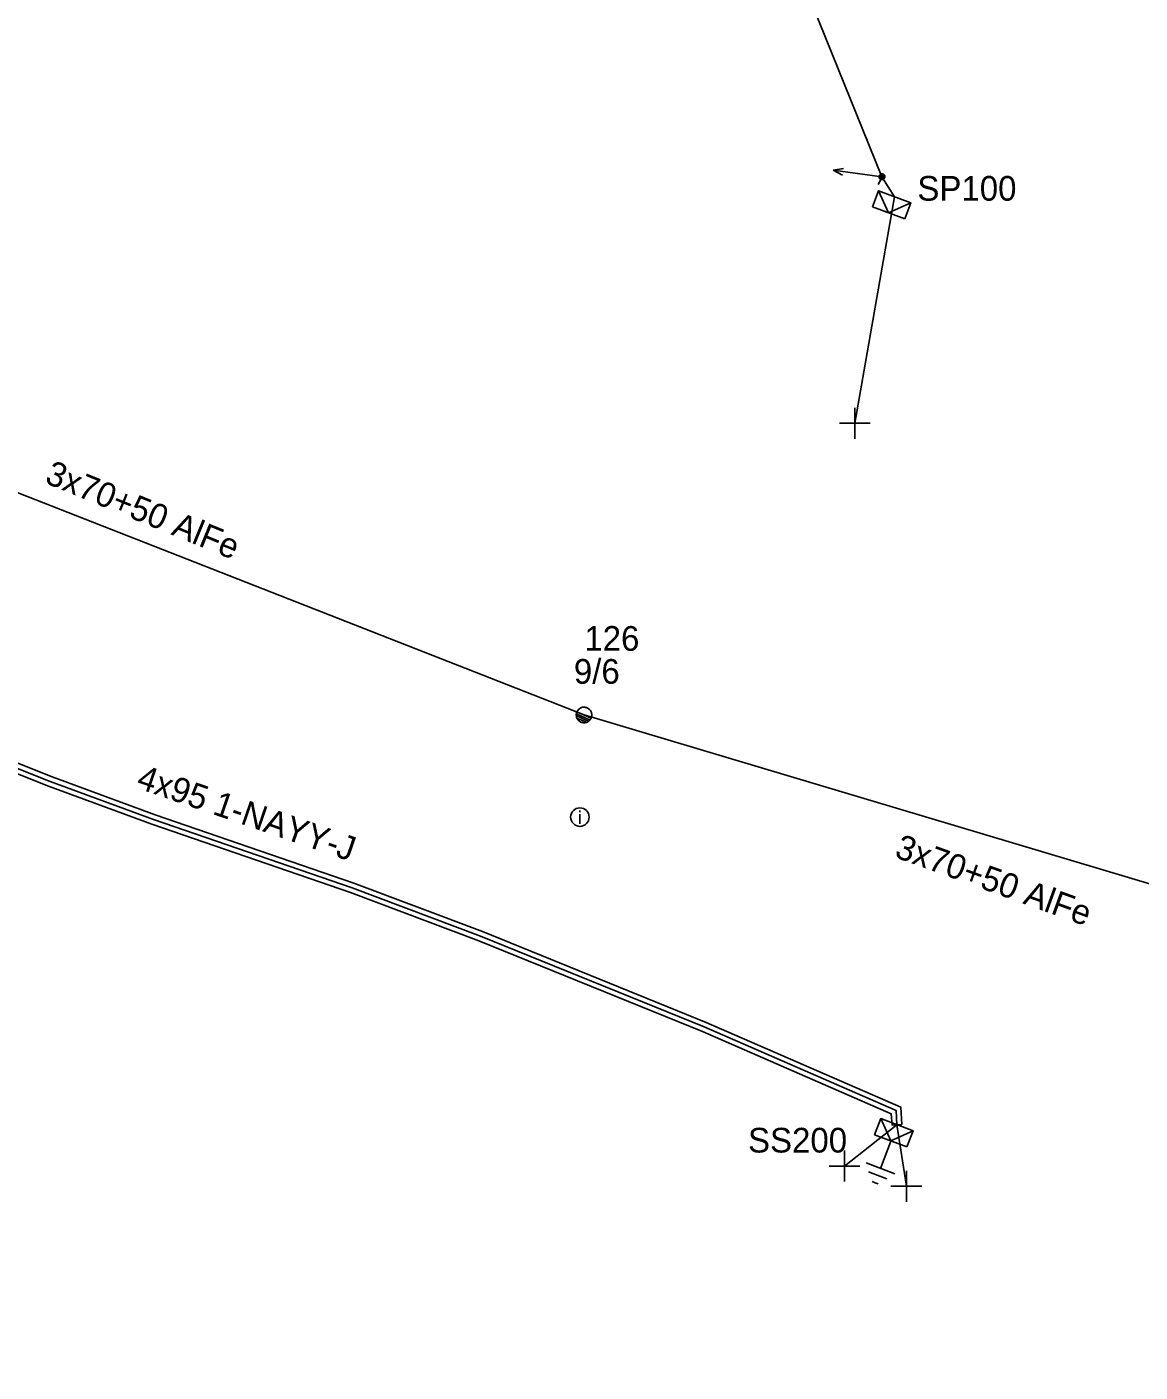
# Model space of a CAD drawing. Extents: x -748492 to -735633, y -1146251 to -1139940.
# Drawn here: x -740483.4 to -740438.3, y -1142129.4 to -1142074.9 of the extents above; entities that cross this region are included whole.
import ezdxf

# ---------------------------------------------------------------- set-up
doc = ezdxf.new("R2010")
doc.units = 0
for name, color, linetype in [('Vrstva 1', 7, 'Continuous'), ('Vrstva 10', 7, 'Continuous'), ('Vrstva 12', 7, 'Continuous'), ('Vrstva 13', 7, 'Continuous'), ('Vrstva 14', 7, 'Continuous'), ('Vrstva 15', 7, 'Continuous'), ('Vrstva 2', 7, 'Continuous'), ('Vrstva 20', 7, 'Continuous'), ('Vrstva 31', 7, 'Continuous'), ('Vrstva 33', 7, 'Continuous'), ('Vrstva 34', 7, 'Continuous'), ('Vrstva 36', 7, 'Continuous'), ('Vrstva 5', 7, 'Continuous'), ('Vrstva 59', 7, 'Continuous'), ('Vrstva 6', 7, 'Continuous'), ('Vrstva 8', 7, 'Continuous'), ('Vrstva 9', 7, 'Continuous')]:
    doc.layers.add(name, color=color, linetype=linetype)

# ---------------------------------------------------------------- blocks, each defined once
blk = doc.blocks.new('NN440')
at = {"layer": 'Vrstva 2'}
for points in [[(0.63, 0), (0.63, 0.06), (0.62, 0.13), (0.6, 0.19), (0.58, 0.25), (0.55, 0.31), (0.51, 0.37), (0.47, 0.42), (0.42, 0.46), (0.37, 0.51), (0.32, 0.54), (0.26, 0.57), (0.2, 0.59), (0.13, 0.61), (0.07, 0.62), (0, 0.63), (-0.06, 0.62), (-0.13, 0.61), (-0.19, 0.59), (-0.26, 0.57), (-0.31, 0.54), (-0.37, 0.51), (-0.42, 0.46), (-0.47, 0.42), (-0.51, 0.37), (-0.54, 0.31), (-0.57, 0.25), (-0.6, 0.19), (-0.62, 0.13), (-0.63, 0.06), (-0.63, 0), (-0.63, -0.07), (-0.62, -0.14), (-0.6, -0.2), (-0.57, -0.26), (-0.54, -0.32), (-0.51, -0.37), (-0.47, -0.43), (-0.42, -0.47), (-0.37, -0.51), (-0.31, -0.55), (-0.26, -0.58), (-0.19, -0.6), (-0.13, -0.62), (-0.06, -0.63), (0, -0.63), (0.07, -0.63), (0.13, -0.62), (0.2, -0.6), (0.26, -0.58), (0.32, -0.55), (0.37, -0.51), (0.42, -0.47), (0.47, -0.43), (0.51, -0.37), (0.55, -0.32), (0.58, -0.26), (0.6, -0.2), (0.62, -0.14), (0.63, -0.07), (0.63, 0)], [(-0.63, 0), (0.63, 0)], [(-0.6, -0.18), (0.57, -0.18)], [(-0.51, -0.32), (0.5, -0.32)], [(-0.37, -0.47), (0.35, -0.47)]]:
    blk.add_lwpolyline(points, dxfattribs=at)
blk = doc.blocks.new('NN560')
at = {"layer": 'Vrstva 2'}
for points in [[(1.999, -0.001), (1.59, 0.141)], [(0, -0.001), (1.999, -0.001)], [(1.999, -0.001), (1.59, -0.134)]]:
    blk.add_lwpolyline(points, dxfattribs=at)
blk = doc.blocks.new('NN770')
at = {"layer": 'Vrstva 10'}
for p, q in [((0.002, 0.187), (0.002, 0.263)), ((0.002, -0.276), (0.002, 0.111))]:
    blk.add_line(p, q, dxfattribs=at)
blk.add_circle((0, -0.008), 0.375, dxfattribs=at)
blk = doc.blocks.new('NN800')
at = {"layer": 'Vrstva 1'}
for points in [[(-0.442, 0.442), (0.442, -0.442)], [(-0.442, -0.442), (0.442, 0.442)]]:
    blk.add_lwpolyline(points, dxfattribs=at)
blk = doc.blocks.new('NN630')
at = {"layer": 'Vrstva 9'}
for points in [[(-0.003, -0.7), (-0.703, 0)], [(-0.703, -0.7), (-0.703, 0), (0.697, 0), (0.697, -0.7)], [(-0.003, -0.7), (0.697, 0)], [(-0.703, -0.7), (0.697, -0.7)]]:
    blk.add_lwpolyline(points, dxfattribs=at)
blk = doc.blocks.new('NN810')
at = {"layer": 'Vrstva 14'}
for points in [[(0.004, -0.64), (0.004, -1.89)], [(0.629, -1.89), (-0.621, -1.89)], [(0.388, -2.2), (-0.399, -2.2)], [(0.004, -2.515), (-0.124, -2.515)], [(0.137, -2.515), (0.004, -2.515)]]:
    blk.add_lwpolyline(points, dxfattribs=at)
blk = doc.blocks.new('NN500')
at = {"layer": 'Vrstva 2'}
for points in [[(0, -0.24), (0.02, -0.23), (0.05, -0.23), (0.07, -0.22), (0.09, -0.22), (0.12, -0.2), (0.14, -0.19), (0.16, -0.18), (0.17, -0.16), (0.19, -0.14), (0.2, -0.12), (0.21, -0.1), (0.22, -0.07), (0.23, -0.05), (0.23, -0.02), (0.23, 0), (0.23, 0.02), (0.23, 0.05), (0.22, 0.07), (0.21, 0.1), (0.2, 0.12), (0.19, 0.14), (0.17, 0.16), (0.16, 0.17), (0.14, 0.19), (0.12, 0.2), (0.09, 0.21), (0.07, 0.22), (0.05, 0.23), (0.02, 0.23), (0, 0.23), (-0.03, 0.23), (-0.05, 0.23), (-0.07, 0.22), (-0.1, 0.21), (-0.12, 0.2), (-0.14, 0.19), (-0.16, 0.17), (-0.18, 0.16), (-0.19, 0.14), (-0.2, 0.12), (-0.22, 0.1), (-0.22, 0.07), (-0.23, 0.05), (-0.23, 0.02), (-0.24, 0), (-0.23, -0.02), (-0.23, -0.05), (-0.22, -0.07), (-0.22, -0.1), (-0.2, -0.12), (-0.19, -0.14), (-0.18, -0.16), (-0.16, -0.18), (-0.14, -0.19), (-0.12, -0.2), (-0.1, -0.22), (-0.07, -0.22), (-0.05, -0.23), (-0.03, -0.23), (0, -0.24)], [(0, -0.24), (0.02, -0.23), (0.05, -0.23), (0.07, -0.22), (0.09, -0.22), (0.12, -0.2), (0.14, -0.19), (0.16, -0.18), (0.17, -0.16), (0.19, -0.14), (0.2, -0.12), (0.21, -0.1), (0.22, -0.07), (0.23, -0.05), (0.23, -0.02), (0.23, 0), (0.23, 0.02), (0.23, 0.05), (0.22, 0.07), (0.21, 0.1), (0.2, 0.12), (0.19, 0.14), (0.17, 0.16), (0.16, 0.17), (0.14, 0.19), (0.12, 0.2), (0.09, 0.21), (0.07, 0.22), (0.05, 0.23), (0.02, 0.23), (0, 0.23), (-0.03, 0.23), (-0.05, 0.23), (-0.07, 0.22), (-0.1, 0.21), (-0.12, 0.2), (-0.14, 0.19), (-0.16, 0.17), (-0.18, 0.16), (-0.19, 0.14), (-0.2, 0.12), (-0.22, 0.1), (-0.22, 0.07), (-0.23, 0.05), (-0.23, 0.02), (-0.24, 0), (-0.23, -0.02), (-0.23, -0.05), (-0.22, -0.07), (-0.22, -0.1), (-0.2, -0.12), (-0.19, -0.14), (-0.18, -0.16), (-0.16, -0.18), (-0.14, -0.19), (-0.12, -0.2), (-0.1, -0.22), (-0.07, -0.22), (-0.05, -0.23), (-0.03, -0.23), (0, -0.24)], [(0, -0.21), (0.02, -0.2), (0.04, -0.2), (0.06, -0.2), (0.08, -0.19), (0.1, -0.18), (0.12, -0.17), (0.14, -0.15), (0.15, -0.14), (0.16, -0.12), (0.18, -0.1), (0.19, -0.08), (0.19, -0.06), (0.2, -0.04), (0.2, -0.02), (0.2, 0), (0.2, 0.02), (0.2, 0.04), (0.19, 0.06), (0.19, 0.08), (0.18, 0.1), (0.16, 0.12), (0.15, 0.14), (0.14, 0.15), (0.12, 0.17), (0.1, 0.18), (0.08, 0.19), (0.06, 0.19), (0.04, 0.2), (0.02, 0.2), (0, 0.2), (-0.02, 0.2), (-0.04, 0.2), (-0.06, 0.19), (-0.08, 0.19), (-0.1, 0.18), (-0.12, 0.17), (-0.14, 0.15), (-0.15, 0.14), (-0.17, 0.12), (-0.18, 0.1), (-0.19, 0.08), (-0.2, 0.06), (-0.2, 0.04), (-0.21, 0.02), (-0.21, 0), (-0.21, -0.02), (-0.2, -0.04), (-0.2, -0.06), (-0.19, -0.08), (-0.18, -0.1), (-0.17, -0.12), (-0.15, -0.14), (-0.14, -0.15), (-0.12, -0.17), (-0.1, -0.18), (-0.08, -0.19), (-0.06, -0.2), (-0.04, -0.2), (-0.02, -0.2), (0, -0.21)], [(0, -0.18), (0.02, -0.18), (0.04, -0.17), (0.05, -0.17), (0.07, -0.16), (0.09, -0.15), (0.1, -0.14), (0.12, -0.13), (0.13, -0.12), (0.14, -0.1), (0.15, -0.09), (0.16, -0.07), (0.17, -0.05), (0.17, -0.04), (0.17, -0.02), (0.17, 0), (0.17, 0.02), (0.17, 0.04), (0.17, 0.05), (0.16, 0.07), (0.15, 0.09), (0.14, 0.1), (0.13, 0.12), (0.12, 0.13), (0.1, 0.14), (0.09, 0.15), (0.07, 0.16), (0.05, 0.17), (0.04, 0.17), (0.02, 0.17), (0, 0.18), (-0.02, 0.17), (-0.04, 0.17), (-0.06, 0.17), (-0.07, 0.16), (-0.09, 0.15), (-0.1, 0.14), (-0.12, 0.13), (-0.13, 0.12), (-0.14, 0.1), (-0.15, 0.09), (-0.16, 0.07), (-0.17, 0.05), (-0.17, 0.04), (-0.18, 0.02), (-0.18, 0), (-0.18, -0.02), (-0.17, -0.04), (-0.17, -0.05), (-0.16, -0.07), (-0.15, -0.09), (-0.14, -0.1), (-0.13, -0.12), (-0.12, -0.13), (-0.1, -0.14), (-0.09, -0.15), (-0.07, -0.16), (-0.06, -0.17), (-0.04, -0.17), (-0.02, -0.18), (0, -0.18)], [(0, -0.15), (0.01, -0.15), (0.03, -0.14), (0.04, -0.14), (0.06, -0.13), (0.07, -0.13), (0.08, -0.12), (0.1, -0.11), (0.11, -0.1), (0.12, -0.09), (0.13, -0.07), (0.13, -0.06), (0.14, -0.05), (0.14, -0.03), (0.14, -0.02), (0.14, 0), (0.14, 0.01), (0.14, 0.03), (0.14, 0.04), (0.13, 0.06), (0.13, 0.07), (0.12, 0.09), (0.11, 0.1), (0.1, 0.11), (0.08, 0.12), (0.07, 0.13), (0.06, 0.13), (0.04, 0.14), (0.03, 0.14), (0.01, 0.14), (0, 0.15), (-0.02, 0.14), (-0.03, 0.14), (-0.05, 0.14), (-0.06, 0.13), (-0.07, 0.13), (-0.09, 0.12), (-0.1, 0.11), (-0.11, 0.1), (-0.12, 0.09), (-0.13, 0.07), (-0.13, 0.06), (-0.14, 0.04), (-0.14, 0.03), (-0.15, 0.01), (-0.15, 0), (-0.15, -0.02), (-0.14, -0.03), (-0.14, -0.05), (-0.13, -0.06), (-0.13, -0.07), (-0.12, -0.09), (-0.11, -0.1), (-0.1, -0.11), (-0.09, -0.12), (-0.07, -0.13), (-0.06, -0.13), (-0.05, -0.14), (-0.03, -0.14), (-0.02, -0.15), (0, -0.15)], [(0, -0.12), (0.01, -0.12), (0.02, -0.11), (0.03, -0.11), (0.05, -0.11), (0.06, -0.1), (0.07, -0.09), (0.08, -0.09), (0.09, -0.08), (0.09, -0.07), (0.1, -0.06), (0.11, -0.05), (0.11, -0.04), (0.11, -0.02), (0.11, -0.01), (0.12, 0), (0.11, 0.01), (0.11, 0.02), (0.11, 0.04), (0.11, 0.05), (0.1, 0.06), (0.09, 0.07), (0.09, 0.08), (0.08, 0.09), (0.07, 0.09), (0.06, 0.1), (0.05, 0.11), (0.03, 0.11), (0.02, 0.11), (0.01, 0.12), (0, 0.12), (-0.01, 0.12), (-0.03, 0.11), (-0.04, 0.11), (-0.05, 0.11), (-0.06, 0.1), (-0.07, 0.09), (-0.08, 0.09), (-0.09, 0.08), (-0.1, 0.07), (-0.1, 0.06), (-0.11, 0.05), (-0.11, 0.04), (-0.12, 0.02), (-0.12, 0.01), (-0.12, 0), (-0.12, -0.01), (-0.12, -0.02), (-0.11, -0.04), (-0.11, -0.05), (-0.1, -0.06), (-0.1, -0.07), (-0.09, -0.08), (-0.08, -0.09), (-0.07, -0.09), (-0.06, -0.1), (-0.05, -0.11), (-0.04, -0.11), (-0.03, -0.11), (-0.01, -0.12), (0, -0.12)], [(0, -0.09), (0.01, -0.09), (0.02, -0.09), (0.03, -0.08), (0.03, -0.08), (0.04, -0.08), (0.05, -0.07), (0.06, -0.07), (0.06, -0.06), (0.07, -0.05), (0.07, -0.04), (0.08, -0.04), (0.08, -0.03), (0.08, -0.02), (0.09, -0.01), (0.09, 0), (0.09, 0.01), (0.08, 0.02), (0.08, 0.03), (0.08, 0.03), (0.07, 0.04), (0.07, 0.05), (0.06, 0.06), (0.06, 0.06), (0.05, 0.07), (0.04, 0.07), (0.03, 0.08), (0.03, 0.08), (0.02, 0.08), (0.01, 0.09), (0, 0.09), (-0.01, 0.09), (-0.02, 0.08), (-0.03, 0.08), (-0.04, 0.08), (-0.04, 0.07), (-0.05, 0.07), (-0.06, 0.06), (-0.07, 0.06), (-0.07, 0.05), (-0.08, 0.04), (-0.08, 0.03), (-0.08, 0.03), (-0.09, 0.02), (-0.09, 0.01), (-0.09, 0), (-0.09, -0.01), (-0.09, -0.02), (-0.08, -0.03), (-0.08, -0.04), (-0.08, -0.04), (-0.07, -0.05), (-0.07, -0.06), (-0.06, -0.07), (-0.05, -0.07), (-0.04, -0.08), (-0.04, -0.08), (-0.03, -0.08), (-0.02, -0.09), (-0.01, -0.09), (0, -0.09)], [(0, -0.06), (0, -0.06), (0.01, -0.06), (0.02, -0.05), (0.02, -0.05), (0.03, -0.05), (0.03, -0.05), (0.04, -0.04), (0.04, -0.04), (0.05, -0.03), (0.05, -0.03), (0.05, -0.02), (0.05, -0.02), (0.05, -0.01), (0.06, -0.01), (0.06, 0), (0.06, 0.01), (0.05, 0.01), (0.05, 0.02), (0.05, 0.02), (0.05, 0.03), (0.05, 0.03), (0.04, 0.04), (0.04, 0.04), (0.03, 0.05), (0.03, 0.05), (0.02, 0.05), (0.02, 0.05), (0.01, 0.06), (0, 0.06), (0, 0.06), (-0.01, 0.06), (-0.01, 0.06), (-0.02, 0.05), (-0.02, 0.05), (-0.03, 0.05), (-0.03, 0.05), (-0.04, 0.04), (-0.04, 0.04), (-0.05, 0.03), (-0.05, 0.03), (-0.05, 0.02), (-0.06, 0.02), (-0.06, 0.01), (-0.06, 0.01), (-0.06, 0), (-0.06, -0.01), (-0.06, -0.01), (-0.06, -0.02), (-0.05, -0.02), (-0.05, -0.03), (-0.05, -0.03), (-0.04, -0.04), (-0.04, -0.04), (-0.03, -0.05), (-0.03, -0.05), (-0.02, -0.05), (-0.02, -0.05), (-0.01, -0.06), (-0.01, -0.06), (0, -0.06)], [(0, -0.03), (0, -0.03), (0, -0.03), (0.01, -0.03), (0.01, -0.03), (0.01, -0.02), (0.02, -0.02), (0.02, -0.02), (0.02, -0.02), (0.02, -0.02), (0.02, -0.01), (0.02, -0.01), (0.03, -0.01), (0.03, -0.01), (0.03, 0), (0.03, 0), (0.03, 0), (0.03, 0.01), (0.03, 0.01), (0.02, 0.01), (0.02, 0.01), (0.02, 0.02), (0.02, 0.02), (0.02, 0.02), (0.02, 0.02), (0.01, 0.02), (0.01, 0.02), (0.01, 0.03), (0, 0.03), (0, 0.03), (0, 0.03), (0, 0.03), (-0.01, 0.03), (-0.01, 0.03), (-0.01, 0.02), (-0.02, 0.02), (-0.02, 0.02), (-0.02, 0.02), (-0.02, 0.02), (-0.02, 0.02), (-0.03, 0.01), (-0.03, 0.01), (-0.03, 0.01), (-0.03, 0.01), (-0.03, 0), (-0.03, 0), (-0.03, 0), (-0.03, -0.01), (-0.03, -0.01), (-0.03, -0.01), (-0.03, -0.01), (-0.02, -0.02), (-0.02, -0.02), (-0.02, -0.02), (-0.02, -0.02), (-0.02, -0.02), (-0.01, -0.03), (-0.01, -0.03), (-0.01, -0.03), (0, -0.03), (0, -0.03)], [(0.23, 0), (0.7, 0)]]:
    blk.add_lwpolyline(points, dxfattribs=at)

msp = doc.modelspace()

# ---------------------------------------------------------------- linework, layer by layer
at = {"layer": 'Vrstva 1'}
msp.add_lwpolyline([(-740499.552, -1142087.621), (-740460.86, -1142102.79), (-740419.1, -1142115.27), (-740400.18, -1142121.15), (-740373.78, -1142129.413)], dxfattribs=at)
at = {"layer": 'Vrstva 20'}
msp.add_lwpolyline([(-740487.302, -1142103.357), (-740482.418, -1142105.303), (-740478.233, -1142106.841), (-740470.182, -1142109.611), (-740464.977, -1142111.563), (-740455.912, -1142115.245), (-740448.028, -1142118.675), (-740447.98, -1142119.376), (-740448.379, -1142119.404), (-740448.411, -1142118.945), (-740456.067, -1142115.614), (-740465.123, -1142111.936), (-740470.317, -1142109.988), (-740478.367, -1142107.218), (-740482.561, -1142105.676), (-740487.518, -1142103.702)], dxfattribs=at)
at = {"layer": 'Vrstva 5'}
msp.add_lwpolyline([(-740448.18, -1142119.39), (-740448.22, -1142118.81), (-740455.99, -1142115.43), (-740465.05, -1142111.75), (-740470.25, -1142109.8), (-740478.3, -1142107.03), (-740482.49, -1142105.49), (-740487.41, -1142103.53), (-740488.86, -1142102.2), (-740492.65, -1142100.91), (-740497.02, -1142103.76), (-740504.1, -1142108.48), (-740504.12, -1142109.13)], dxfattribs=at)
at = {"layer": 'Vrstva 59'}
for points in [[(-740448.275, -1142081.8), (-740449.888, -1142090.973)], [(-740448.18, -1142119.39), (-740450.307, -1142121.067)], [(-740448.18, -1142119.39), (-740447.799, -1142121.886)]]:
    msp.add_lwpolyline(points, dxfattribs=at)
at = {"layer": 'Vrstva 8'}
msp.add_lwpolyline([(-740460.21, -1142052.751), (-740448.79, -1142080.99), (-740448.275, -1142081.8)], dxfattribs=at)

# ---------------------------------------------------------------- block references
at = {"layer": 'Vrstva 13', "rotation": 172.43760841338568}
msp.add_blockref('NN560', (-740448.791, -1142080.989), dxfattribs=at)
at = {"layer": 'Vrstva 13', "xscale": 0.5}
for name, p, yscale, rotation in [('NN500', (-740448.79, -1142080.989), 0.5000000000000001, -115.5893828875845), ('NN440', (-740460.86, -1142102.79), 0.5, -24.111127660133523)]:
    msp.add_blockref(name, p, dxfattribs=dict(at, yscale=yscale, rotation=rotation))
at = {"layer": 'Vrstva 15', "rotation": -20.73673895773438}
msp.add_blockref('NN810', (-740448.18, -1142119.39), dxfattribs=at)
at = {"layer": 'Vrstva 31'}
for p, rotation in [((-740448.276, -1142081.8), -20.29697500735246), ((-740448.18, -1142119.39), -20.73673895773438)]:
    msp.add_blockref('NN630', p, dxfattribs=dict(at, rotation=rotation))
at = {"layer": 'Vrstva 34'}
for p, rotation in [((-740449.888, -1142090.973), 45), ((-740450.307, -1142121.067), 45), ((-740447.799, -1142121.886), 45.00000009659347)]:
    msp.add_blockref('NN800', p, dxfattribs=dict(at, rotation=rotation))
at = {"layer": 'Vrstva 36'}
msp.add_blockref('NN770', (-740461.028, -1142106.921), dxfattribs=at)

# ---------------------------------------------------------------- texts
at = {"layer": 'Vrstva 12'}
msp.add_text('9/6', height=1, dxfattribs=at).set_placement((-740461.273, -1142101.526))
at = {"layer": 'Vrstva 14'}
msp.add_text('126', height=1, dxfattribs=at).set_placement((-740460.849, -1142100.191))
at = {"layer": 'Vrstva 2'}
for rotation, p in [(337.751, (-740482.756, -1142093.374)), (340.134, (-740448.323, -1142108.538))]:
    msp.add_text('3x70+50 AlFe', height=1, rotation=rotation, dxfattribs=at).set_placement(p)
at = {"layer": 'Vrstva 33'}
for s, p in [('SP100', (-740447.354, -1142081.957)), ('SS200', (-740454.216, -1142120.518))]:
    msp.add_text(s, height=1, dxfattribs=at).set_placement(p)
at = {"layer": 'Vrstva 6'}
msp.add_text('4x95 1-NAYY-J', height=1, rotation=341.012, dxfattribs=at).set_placement((-740479.046, -1142105.731))

doc.saveas('drawing.dxf')
